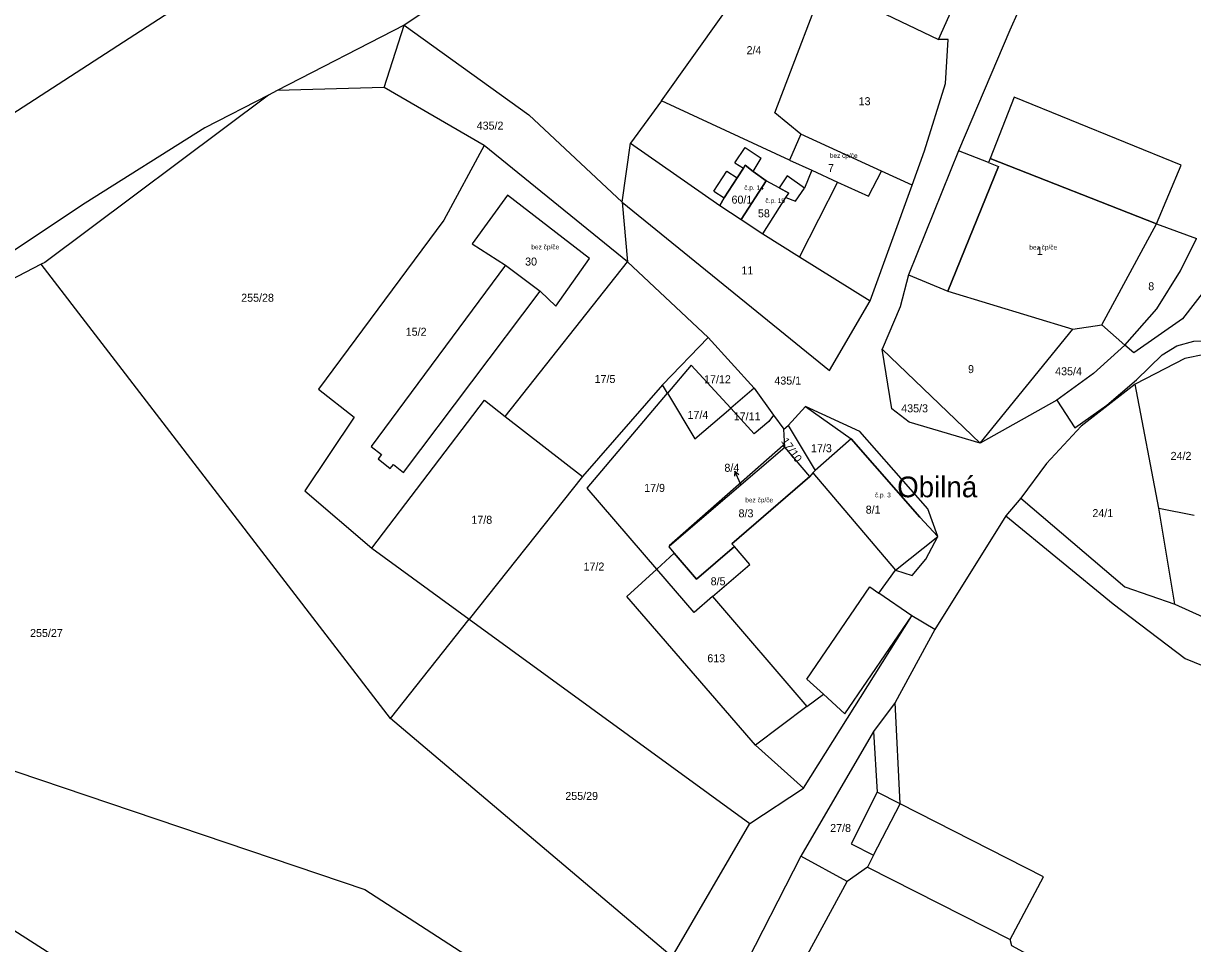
# Model space of a CAD drawing. Extents: x -882150 to -879379, y -1022570 to -1019819.
# Drawn here: x -880738 to -880489.6, y -1021365.7 to -1021170.2 of the extents above; entities that cross this region are included whole.
import ezdxf

# ---------------------------------------------------------------- set-up
doc = ezdxf.new("R2010")
doc.units = 0
for name, color, linetype in [('Definiční body', 7, 'Continuous'), ('Hranice parcel', 7, 'Continuous'), ('Parcelní čísla', 7, 'Continuous'), ('Polygon budovy', 7, 'Continuous'), ('Pop  PČ popisy', 7, 'Continuous'), ('Vnitřní kresba', 7, 'Continuous')]:
    doc.layers.add(name, color=color, linetype=linetype)

msp = doc.modelspace()

# ---------------------------------------------------------------- linework, layer by layer
at = {"layer": 'Hranice parcel'}
for p, q in [((-880602.77, -1021134.34), (-880657.13, -1021170.56)), ((-880661.35, -1021183.81), (-880657.13, -1021170.56)), ((-880684.13, -1021184.49), (-880685.95, -1021185.43)), ((-880661.35, -1021183.81), (-880684.13, -1021184.49)), ((-880640.11, -1021196.16), (-880661.35, -1021183.81)), ((-880602.45, -1021186.68), (-880609.03, -1021195.67)), ((-880575.27, -1021199.23), (-880602.45, -1021186.68)), ((-880610.78, -1021208.19), (-880609.03, -1021195.67)), ((-880572.81, -1021193.74), (-880575.27, -1021199.23)), ((-880609.7, -1021220.83), (-880640.11, -1021196.16)), ((-880539.35, -1021197.25), (-880549.94, -1021223.64)), ((-880575.27, -1021199.23), (-880570.51, -1021201.41)), ((-880558.09, -1021229.15), (-880549.21, -1021204.6)), ((-880610.78, -1021208.19), (-880609.7, -1021220.83)), ((-880508.88, -1021234.25), (-880497.26, -1021212.75)), ((-880497.26, -1021212.75), (-880488.78, -1021215.92)), ((-880635.66, -1021253.7), (-880609.7, -1021220.83)), ((-880592.5, -1021236.92), (-880609.7, -1021220.83)), ((-880573.11, -1021219.79), (-880558.09, -1021229.15)), ((-880660.06, -1021317.87), (-880734.24, -1021221.36)), ((-880534.73, -1021259.38), (-880515.07, -1021235.18)), ((-880515.07, -1021235.18), (-880508.88, -1021234.25)), ((-880508.88, -1021234.25), (-880503.97, -1021238.53)), ((-880602.26, -1021246.99), (-880592.5, -1021236.92)), ((-880592.5, -1021236.92), (-880582.78, -1021247.68)), ((-880555.55, -1021239.39), (-880534.73, -1021259.38)), ((-880553.51, -1021252.07), (-880555.55, -1021239.39)), ((-880602.26, -1021246.99), (-880619.24, -1021266.45)), ((-880601.19, -1021248.78), (-880602.26, -1021246.99)), ((-880582.78, -1021247.68), (-880587.74, -1021251.95)), ((-880582.78, -1021247.68), (-880578.62, -1021253.43)), ((-880496.75, -1021273.23), (-880501.78, -1021246.86)), ((-880518.44, -1021250.25), (-880534.73, -1021259.38)), ((-880571.85, -1021251.6), (-880575.52, -1021255.6)), ((-880549.81, -1021254.92), (-880553.51, -1021252.07)), ((-880635.66, -1021253.7), (-880619.24, -1021266.45)), ((-880578.62, -1021253.43), (-880576.45, -1021256.43)), ((-880576.45, -1021256.43), (-880575.52, -1021255.6)), ((-880575.52, -1021255.6), (-880569.82, -1021265.22)), ((-880534.73, -1021259.38), (-880549.81, -1021254.92)), ((-880576.21, -1021260.26), (-880576.45, -1021256.43)), ((-880576.27, -1021260.3), (-880600.72, -1021281.3)), ((-880576.21, -1021260.26), (-880576.27, -1021260.3)), ((-880570.93, -1021266.47), (-880576.21, -1021260.26)), ((-880619.24, -1021266.45), (-880643.31, -1021296.77)), ((-880570.93, -1021266.47), (-880587.47, -1021280.76)), ((-880526.13, -1021271.04), (-880529.31, -1021274.86)), ((-880529.31, -1021274.86), (-880544.36, -1021298.96)), ((-880493.37, -1021293.62), (-880496.75, -1021273.23)), ((-880496.75, -1021273.23), (-880489.23, -1021274.65)), ((-880663.97, -1021281.71), (-880643.31, -1021296.77)), ((-880599.75, -1021282.74), (-880603.45, -1021286.13)), ((-880587.47, -1021280.76), (-880586.95, -1021281.37)), ((-880660.06, -1021317.87), (-880643.31, -1021296.77)), ((-880643.31, -1021296.77), (-880583.69, -1021340.23)), ((-880572.25, -1021332.66), (-880549.24, -1021296.04)), ((-880544.36, -1021298.96), (-880549.24, -1021296.04)), ((-880544.36, -1021298.96), (-880552.77, -1021314.46)), ((-880551.77, -1021336.02), (-880552.77, -1021314.46)), ((-880600.19, -1021368.5), (-880660.06, -1021317.87)), ((-880582.47, -1021323.52), (-880572.25, -1021332.66)), ((-880583.69, -1021340.23), (-880572.25, -1021332.66)), ((-880600.19, -1021368.5), (-880583.69, -1021340.23))]:
    msp.add_line(p, q, dxfattribs=at)
for points in [[(-880602.45, -1021186.68), (-880589.43, -1021168.38), (-880587.64, -1021162.87), (-880580.4, -1021148.8)], [(-880572.81, -1021193.74), (-880578.34, -1021189.21), (-880566, -1021156.7)], [(-880566, -1021156.7), (-880560.4, -1021159.2), (-880562.3, -1021164.6), (-880556.46, -1021167.45), (-880543.6, -1021173.6)], [(-880699.29, -1021162.79), (-880808.35, -1021233.5), (-880873.35, -1021274.78), (-880941.52, -1021318.31), (-881007.7, -1021360.64), (-881104.49, -1021422.63)], [(-880543.6, -1021173.6), (-880540.67, -1021167.18), (-880535.26, -1021161.4), (-880525.8, -1021164)], [(-880525.8, -1021164), (-880526.67, -1021167.7), (-880528.44, -1021171.66), (-880539.35, -1021197.25)], [(-880657.13, -1021170.56), (-880630.62, -1021189.66), (-880610.78, -1021208.19)], [(-880549.21, -1021204.6), (-880546.57, -1021197.29), (-880542.08, -1021183), (-880541.56, -1021173.61), (-880543.6, -1021173.6)], [(-880685.95, -1021185.43), (-880733.48, -1021220.97), (-880734.24, -1021221.36)], [(-880497.26, -1021212.75), (-880492.02, -1021200.33), (-880527.51, -1021185.87), (-880532.64, -1021198.87), (-880532.99, -1021199.76), (-880539.35, -1021197.25)], [(-880473.96, -1021187.71), (-880477.55, -1021197.73), (-880482.75, -1021218.18), (-880486.35, -1021226.03), (-880491.71, -1021232.97), (-880502.05, -1021240.2), (-880503.97, -1021238.53)], [(-880518.44, -1021250.25), (-880514.62, -1021256.12), (-880507.85, -1021251.3), (-880501.52, -1021245.91), (-880496.1, -1021240.64), (-880492.92, -1021238.71), (-880489.34, -1021237.69), (-880485.62, -1021237.66), (-880482.02, -1021238.6), (-880479.01, -1021240.25), (-880471.89, -1021236.03), (-880478.16, -1021217.09), (-880475.5, -1021210.72), (-880473.54, -1021204.78), (-880469.31, -1021188.85)], [(-880609.03, -1021195.67), (-880590.04, -1021208.86), (-880585.54, -1021211.87)], [(-880549.21, -1021204.6), (-880555.68, -1021201.63), (-880572.81, -1021193.74)], [(-880640.11, -1021196.16), (-880648.7, -1021212.02), (-880675.32, -1021247.93), (-880667.72, -1021253.89), (-880678.26, -1021269.48), (-880663.97, -1021281.71)], [(-880570.51, -1021201.41), (-880572.08, -1021205.18), (-880575.78, -1021202.6), (-880577.44, -1021205.12), (-880580.21, -1021203.62), (-880585.54, -1021211.87)], [(-880570.51, -1021201.41), (-880565.05, -1021203.91), (-880573.11, -1021219.79)], [(-880660.1, -1021264.79), (-880659.38, -1021263.9), (-880657.25, -1021265.62), (-880628.23, -1021227.08), (-880624.89, -1021230.28), (-880617.72, -1021220.17), (-880635.14, -1021206.73), (-880642.65, -1021217.05), (-880635.61, -1021221.58), (-880664.11, -1021260.06), (-880661.96, -1021261.8), (-880662.68, -1021262.69), (-880660.1, -1021264.79)], [(-880610.78, -1021208.19), (-880566.73, -1021243.92), (-880558.09, -1021229.15)], [(-880585.54, -1021211.87), (-880580.91, -1021214.93), (-880573.11, -1021219.79)], [(-880503.97, -1021238.53), (-880497.17, -1021230.88), (-880492.15, -1021222.79), (-880488.78, -1021215.92)], [(-880734.24, -1021221.36), (-880777.81, -1021244), (-880800.04, -1021257.88), (-880834.2, -1021278.73), (-880852.86, -1021290.89)], [(-880549.94, -1021223.64), (-880551.76, -1021230.43), (-880555.55, -1021239.39)], [(-880549.94, -1021223.64), (-880541.6, -1021227.12), (-880515.07, -1021235.18)], [(-880503.97, -1021238.53), (-880510.64, -1021244.58), (-880518.44, -1021250.25)], [(-880474.8, -1021254.79), (-880474.36, -1021244.16), (-880474.25, -1021241.54), (-880476.39, -1021241.38), (-880487.08, -1021240.58), (-880491.24, -1021241.37), (-880501.78, -1021246.86)], [(-880587.74, -1021251.95), (-880596.12, -1021242.78), (-880601.19, -1021248.78)], [(-880501.78, -1021246.86), (-880513.29, -1021255.74), (-880520.64, -1021263.73), (-880526.13, -1021271.04)], [(-880663.97, -1021281.71), (-880640.08, -1021250.27), (-880635.66, -1021253.7)], [(-880603.45, -1021286.13), (-880618.25, -1021268.95), (-880601.19, -1021248.78)], [(-880601.19, -1021248.78), (-880595.35, -1021258.5), (-880587.74, -1021251.95)], [(-880578.62, -1021253.43), (-880579.62, -1021254.79), (-880582.78, -1021257.38), (-880587.74, -1021251.95)], [(-880549.24, -1021296.04), (-880556.3, -1021291.23), (-880552.71, -1021286.35), (-880549.16, -1021287.48), (-880546.25, -1021284), (-880543.76, -1021279.24), (-880545.84, -1021273.35), (-880560.34, -1021256.93), (-880571.85, -1021251.6)], [(-880571.85, -1021251.6), (-880562.14, -1021258.44), (-880569.82, -1021265.22)], [(-880576.27, -1021260.3), (-880576.61, -1021259.91), (-880600.81, -1021281.19), (-880600.72, -1021281.3)], [(-880569.82, -1021265.22), (-880570.32, -1021265.66), (-880570.93, -1021266.47)], [(-880526.13, -1021271.04), (-880504.01, -1021289.9), (-880493.37, -1021293.62)], [(-880529.31, -1021274.86), (-880506.49, -1021293.52), (-880491.17, -1021305.16), (-880467.02, -1021315.01), (-880447.92, -1021320.85), (-880429.84, -1021330.36), (-880427.85, -1021339.96)], [(-880600.72, -1021281.3), (-880600.87, -1021281.44), (-880599.75, -1021282.74)], [(-880586.95, -1021281.37), (-880594.98, -1021288.3), (-880599.75, -1021282.74)], [(-880591.58, -1021291.98), (-880583.68, -1021285.16), (-880586.95, -1021281.37)], [(-880582.47, -1021323.52), (-880609.82, -1021291.97), (-880603.45, -1021286.13)], [(-880591.58, -1021291.98), (-880595.49, -1021295.36), (-880603.45, -1021286.13)], [(-880852.86, -1021290.89), (-880665.52, -1021354.25), (-880609.55, -1021390.4)], [(-880650.52, -1021420.19), (-880751.74, -1021355.5), (-880852.86, -1021290.89)], [(-880591.58, -1021291.98), (-880571.6, -1021315.37), (-880582.47, -1021323.52)], [(-880493.37, -1021293.62), (-880484.47, -1021297.65), (-880464.66, -1021305.36)], [(-880552.77, -1021314.46), (-880557.4, -1021320.65), (-880572.87, -1021347.16)], [(-880551.77, -1021336.02), (-880556.59, -1021333.55), (-880562.16, -1021344.48), (-880557.37, -1021346.94), (-880558.66, -1021349.45), (-880562.99, -1021352.49), (-880572.87, -1021347.16)], [(-880546.66, -1021419.56), (-880544.76, -1021416.1), (-880536.71, -1021401.44), (-880519.81, -1021370.66), (-880528.01, -1021366.19), (-880528.37, -1021364.81), (-880521.3, -1021351.55), (-880551.77, -1021336.02)], [(-880572.87, -1021347.16), (-880585.84, -1021372.47), (-880591.22, -1021381.45)]]:
    msp.add_lwpolyline(points, dxfattribs=at)
at = {"layer": 'Polygon budovy'}
for points in [[(-880575.27, -1021199.23), (-880570.51, -1021201.41), (-880565.05, -1021203.91), (-880558.49, -1021206.91), (-880555.68, -1021201.63), (-880572.81, -1021193.74)], [(-880582.98, -1021201.65), (-880584.66, -1021200.35), (-880585.06, -1021200.96), (-880586.36, -1021202.98), (-880589.13, -1021207.27), (-880590.04, -1021208.86), (-880585.54, -1021211.87), (-880580.21, -1021203.62)], [(-880508.88, -1021234.25), (-880497.26, -1021212.75), (-880532.64, -1021198.87), (-880532.99, -1021199.76), (-880530.85, -1021200.61), (-880541.6, -1021227.12), (-880515.07, -1021235.18)], [(-880585.54, -1021211.87), (-880580.91, -1021214.93), (-880576.02, -1021207.19), (-880575.42, -1021206.24), (-880577.44, -1021205.12), (-880580.21, -1021203.62)], [(-880642.65, -1021217.05), (-880635.61, -1021221.58), (-880628.23, -1021227.08), (-880624.89, -1021230.28), (-880617.72, -1021220.17), (-880635.14, -1021206.73)], [(-880576.21, -1021260.26), (-880576.27, -1021260.3), (-880600.72, -1021281.3), (-880600.87, -1021281.44), (-880599.75, -1021282.74), (-880594.98, -1021288.3), (-880586.95, -1021281.37), (-880587.47, -1021280.76), (-880570.93, -1021266.47)], [(-880570.32, -1021265.66), (-880552.71, -1021286.35), (-880543.76, -1021279.24), (-880547.53, -1021275.14), (-880562.14, -1021258.44), (-880569.82, -1021265.22)]]:
    msp.add_lwpolyline(points, close=True, dxfattribs=at)
at = {"layer": 'Pop  PČ popisy'}
for p, q in [((-880586.891, -1021265.308), (-880586.941, -1021266.427)), ((-880585.67, -1021268.05), (-880586.891, -1021265.308)), ((-880586.891, -1021265.308), (-880586.026, -1021266.02)), ((-880585.63, -1021268.14), (-880585.67, -1021268.05))]:
    msp.add_line(p, q, dxfattribs=at)
at = {"layer": 'Vnitřní kresba'}
for p, q in [((-880657.13, -1021170.56), (-880684.13, -1021184.49)), ((-880685.95, -1021185.43), (-880699.48, -1021192.4)), ((-880699.48, -1021192.4), (-880724.89, -1021208.38)), ((-880586.84, -1021199.82), (-880584.65, -1021196.55)), ((-880584.65, -1021196.55), (-880581.26, -1021198.85)), ((-880586.84, -1021199.82), (-880585.06, -1021200.96)), ((-880586.36, -1021202.98), (-880585.06, -1021200.96)), ((-880585.06, -1021200.96), (-880584.66, -1021200.35)), ((-880584.66, -1021200.35), (-880582.98, -1021201.65)), ((-880582.98, -1021201.65), (-880581.26, -1021198.85)), ((-880541.6, -1021227.12), (-880530.85, -1021200.61)), ((-880532.99, -1021199.76), (-880530.85, -1021200.61)), ((-880532.64, -1021198.87), (-880497.26, -1021212.75)), ((-880591.31, -1021205.87), (-880588.54, -1021201.58)), ((-880589.13, -1021207.27), (-880586.36, -1021202.98)), ((-880588.54, -1021201.58), (-880586.36, -1021202.98)), ((-880582.98, -1021201.65), (-880580.21, -1021203.62)), ((-880558.49, -1021206.91), (-880555.68, -1021201.63)), ((-880591.31, -1021205.87), (-880589.13, -1021207.27)), ((-880577.44, -1021205.12), (-880575.42, -1021206.24)), ((-880574, -1021207.95), (-880572.08, -1021205.18)), ((-880565.05, -1021203.91), (-880558.49, -1021206.91)), ((-880724.89, -1021208.38), (-880758.2, -1021230.44)), ((-880590.04, -1021208.86), (-880589.13, -1021207.27)), ((-880580.91, -1021214.93), (-880576.02, -1021207.19)), ((-880576.02, -1021207.19), (-880575.42, -1021206.24)), ((-880576.02, -1021207.19), (-880574, -1021207.95)), ((-880635.61, -1021221.58), (-880628.23, -1021227.08)), ((-880562.14, -1021258.44), (-880547.53, -1021275.14)), ((-880570.32, -1021265.66), (-880552.71, -1021286.35)), ((-880547.53, -1021275.14), (-880543.76, -1021279.24)), ((-880552.71, -1021286.35), (-880543.76, -1021279.24)), ((-880571.55, -1021309.52), (-880558.2, -1021289.93)), ((-880558.2, -1021289.93), (-880556.3, -1021291.23)), ((-880563.48, -1021316.87), (-880549.24, -1021296.04)), ((-880571.55, -1021309.52), (-880568.05, -1021312.71)), ((-880571.6, -1021315.37), (-880568.05, -1021312.71)), ((-880568.05, -1021312.71), (-880563.48, -1021316.87)), ((-880557.4, -1021320.65), (-880556.59, -1021333.55)), ((-880557.37, -1021346.94), (-880551.77, -1021336.02)), ((-880558.66, -1021349.45), (-880528.37, -1021364.81)), ((-880576.66, -1021377.55), (-880562.99, -1021352.49))]:
    msp.add_line(p, q, dxfattribs=at)

# ---------------------------------------------------------------- texts
at = {"layer": 'Definiční body'}
for s, p in [('bez čp/če', (-880566.68, -1021198.77)), ('č.p. 14', (-880584.87, -1021205.6)), ('č.p. 15', (-880580.37, -1021208.36)), ('bez čp/če', (-880630.1, -1021218.2)), ('bez čp/če', (-880524.29, -1021218.27)), ('č.p. 3', (-880557.1, -1021270.9)), ('bez čp/če', (-880584.65, -1021271.96))]:
    msp.add_text(s, height=1, dxfattribs=at).set_placement(p)
at = {"layer": 'Parcelní čísla'}
for s, p in [('2/4', (-880584.37, -1021176.74)), ('13', (-880560.56, -1021187.58)), ('435/2', (-880641.725, -1021192.77)), ('7', (-880567.08, -1021201.78)), ('60/1', (-880587.57, -1021208.49)), ('58', (-880581.96, -1021211.41)), ('1', (-880522.71, -1021219.41)), ('30', (-880631.43, -1021221.65)), ('11', (-880585.47, -1021223.54)), ('8', (-880499.02, -1021226.9)), ('255/28', (-880691.76, -1021229.34)), ('15/2', (-880656.8, -1021236.56)), ('9', (-880537.31, -1021244.5)), ('435/4', (-880518.804, -1021244.96)), ('17/5', (-880616.67, -1021246.6)), ('17/12', (-880593.405, -1021246.66)), ('435/1', (-880578.471, -1021246.94)), ('17/4', (-880596.93, -1021254.23)), ('17/11', (-880587.101, -1021254.54)), ('435/3', (-880551.511, -1021252.83)), ('17/3', (-880570.68, -1021261.31)), ('24/2', (-880494.27, -1021262.94)), ('8/4', (-880589.081, -1021265.47)), ('17/9', (-880606.131, -1021269.74)), ('8/1', (-880559.06, -1021274.36)), ('17/8', (-880642.85, -1021276.52)), ('8/3', (-880586.078, -1021275.14)), ('24/1', (-880510.89, -1021275.1)), ('17/2', (-880619.02, -1021286.45)), ('8/5', (-880592.005, -1021289.58)), ('255/27', (-880736.62, -1021300.57)), ('613', (-880592.709, -1021305.94)), ('255/29', (-880622.89, -1021335.19)), ('27/8', (-880566.61, -1021342))]:
    msp.add_text(s, height=1.7, dxfattribs=at).set_placement(p)
msp.add_text('17/10', height=1.7, rotation=305, dxfattribs=at).set_placement((-880577.117, -1021258.97))
at = {"layer": 'Pop  PČ popisy'}
msp.add_text('Obilná', height=4.4, dxfattribs=at).set_placement((-880552.373, -1021270.88))

doc.saveas('drawing.dxf')
